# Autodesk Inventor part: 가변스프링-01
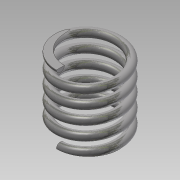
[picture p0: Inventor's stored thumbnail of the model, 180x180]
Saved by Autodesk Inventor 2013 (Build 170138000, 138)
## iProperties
Created: 2014-12
Part Number: 가변스프링-01
Material: 강철, 탄소
Document SubType Name: Modeling
Designer: hanacad19
Density: 7.87 g/cm^3
Mass: 18.7452 g
Surface Area: 32.4001 cm^2
Volume: 2.38185 cm^3
Author: hanacad19
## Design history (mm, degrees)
sketch "스케치1"
  geometry: L1 (0, 0)-(-11, 0); L2 (-11, 0)-(-11, 25.358); L3 (-11, 25.358)-(0, 25.358); L4 (0, 25.358)-(0, 0); C1 r 1.5 at (-11, 0)
  constraints: 8 end point, 2 parallel, 1 centre point, 1 horizontal, 1 perpendicular
  dimensions: "d0" = 3 diameter of C1; "d2" = 22 diameter of L2 L4; "d3" = 25.35829 distance between parallel lines of L1 L3 (derived)
feature "코일1" sketch "스케치1" pitch "d4" = 10; turns "d6" = 5; dims "d5" = 25.35829 (= d3), "d7" = 0, angle "d8" = 90 deg, angle "d9" = 90 deg, "d10" = 0, "d11" = 0
sketch "스케치2"
  geometry: L1 (0, -12.5)-(0, -9.5) reference; 1 further point
  constraints: 1 vertical alignment
extrude "돌출1" cut sketch "스케치2" distance "d12" = 10; taper "d13" = 0 deg
node "작업 평면1"
sketch "스케치3"
  geometry: L1 (0, -9.5)-(0, -12.5) reference; 1 further point
  constraints: 1 vertical alignment
extrude "돌출2" cut sketch "스케치3" distance "d14" = 10; taper "d15" = 0 deg
node "솔리드1"
node "절단 모서리 투영1"
node "절단 모서리 투영2"
